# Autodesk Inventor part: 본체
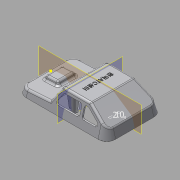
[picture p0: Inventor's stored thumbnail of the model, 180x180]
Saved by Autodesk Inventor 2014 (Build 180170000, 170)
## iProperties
Created: 2015-05
Part Number: 본체
Material: ABS 플라스틱
Document SubType Name: Modeling
Designer: Administrator
Density: 1.06 g/cm^3
Appearance: 매끄러움 - 흰색
Mass: 32.1363 g
Surface Area: 313.722 cm^2
Volume: 30.3172 cm^3
Author: Administrator
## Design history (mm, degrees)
sketch "스케치2"
  geometry: L1 (-49, -38)-(49, -38); L2 (61, -26)-(61, 26); L3 (49, 38)-(-49, 38); L4 (-61, 26)-(-61, -26); L5 (-61, -38)-(61, 38); L6 (61, -38)-(-61, 38); A1 r 12 centre (-49, 26) between (-49, 38) and (-61, 26); A2 r 12 centre (-49, -26) between (-61, -26) and (-49, -38); A3 r 12 centre (49, -26) between (49, -38) and (61, -26); A4 r 12 centre (49, 26) between (61, 26) and (49, 38); 1 further point
  constraints: 12 end point, 8 point on circle, 8 point on line, 8 tangent, 4 centre point, 3 equal radius, 2 midpoint, 2 parallel, 1 horizontal, 1 perpendicular
  dimensions: "d1" = 122 distance of L5.end L6.end; "d2" = 76 distance of L6.start L5.end; "d3" = 12 radius of A1
extrude "돌출1" new body sketch "스케치2" distance "d4" = 30; taper "d5" = -15 deg
sketch "스케치3"
  geometry: L1 (-61, 0)-(-49, 0) reference; L2 (49, 30)-(-49, 30) reference; L3 (-61, 30)-(-31, 30); L4 (-31, 30)-(-61, 10); L5 (-61, 10)-(-61, 30); 2 further points
  constraints: 6 end point, 1 horizontal, 1 midpoint, 1 perpendicular, 1 point on line, 1 vertical alignment
  dimensions: "d6" = 20 distance of L4.end L3.start; "d7" = 30 distance of L3.start L3.end
extrude "돌출2" cut sketch "스케치3" stored distance "d8" = 30; taper "d9" = 0 deg
sketch "스케치4"
  geometry: L1 (49, 0)-(61, 0) reference; L2 (61, 0)-(61, 8); L3 (61, 0)-(52.962, 30) reference; L4 (49, 30)-(-31, 30) reference; L5 (58.826, 8.114)-(19, 10.201); L6 (19, 10.201)-(6.628, 30); L7 (58.826, 8.114)-(58.826, 30); L8 (58.826, 30)-(6.628, 30); L9 (58.826, 8.114)-(61, 8); 1 further point
  constraints: 12 end point, 2 collinear, 2 perpendicular, 2 point on line
  dimensions: "d11" = 42 horizontal distance of L5.end L1.end; "d12" = 125 deg angle of L6 L5; "d13" = 3 deg angle of L5 L1; "d14" = 8 distance of L1.end L2.end
extrude "돌출3" cut sketch "스케치4" stored distance "d15" = 30; taper "d16" = 0 deg
sketch "스케치5"
  geometry: L1 (49, 38)-(-49, 38) reference; L2 (-61, 26)-(-61, -26) reference; L3 (-49, -38)-(49, -38) reference; L4 (61, -26)-(61, 26) reference; A1 r 12 centre (-49, 26) between (-49, 38) and (-61, 26) reference; A2 r 12 centre (-49, -26) between (-61, -26) and (-49, -38) reference; A3 r 12 centre (49, -26) between (49, -38) and (61, -26) reference; A4 r 12 centre (49, 26) between (61, 26) and (49, 38) reference; 1 further point
sketch "스케치6"
  geometry: L1 (-39.881, 9.267)-(-39.881, 61.267) reference; L2 (-31.476, 48.267)-(-11.476, 48.267); L3 (-11.476, 48.267)-(-11.476, 22.267); L4 (-11.476, 22.267)-(-31.476, 22.267); L5 (-31.476, 22.267)-(-31.476, 48.267); L6 (-31.476, 48.267)-(-11.476, 22.267); L7 (-11.476, 48.267)-(-31.476, 22.267); L8 (-42.476, 9.267)-(-42.476, 61.267) reference; 4 further points
  constraints: 12 end point, 4 midpoint, 2 parallel, 1 horizontal, 1 horizontal alignment, 1 perpendicular
  dimensions: "d17" = 20 distance of L3.end L4.end; "d18" = 26 distance of L2.end L3.end; "d19" = 11 distance between parallel lines of L8 L5
extrude "돌출4" join sketch "스케치6" distance "d20" = 5; taper "d21" = -20 deg
fillet "모깎기1" dims "d22" = 3
fillet "모깎기2" dims "d23" = 3
sketch "스케치7"
  geometry: 1 further point
sketch "스케치8"
  geometry: L1 (-50.664, 16.891)-(-31.756, 29.496) reference; L2 (-61, 0)-(-58.03, 11.082) reference; 1 further point
feature "쉘1" dims "d24" = 2
sketch "스케치9"
  geometry: L1 (-58.929, -26)-(-58.929, 26) reference; L2 (-49, 35.929)-(49, 35.929) reference; L3 (58.929, 26)-(58.929, -26) reference; L4 (49, -35.929)-(-49, -35.929) reference; L5 (49, 35.882)-(-49, 35.882); L6 (-58.882, 26)-(-58.882, -26); L7 (-49, -35.882)-(49, -35.882); L8 (58.882, -26)-(58.882, 26); L9 (49, 36.929)-(-49, 36.929); L10 (-59.929, 26)-(-59.929, -26); L11 (-49, -36.929)-(49, -36.929); L12 (59.929, -26)-(59.929, 26); A1 r 9.929 centre (-49, -26) between (-58.929, -26) and (-49, -35.929) reference; A2 r 9.929 centre (-49, 26) between (-49, 35.929) and (-58.929, 26) reference; A3 r 9.929 centre (49, 26) between (58.929, 26) and (49, 35.929) reference; A4 r 9.929 centre (49, -26) between (49, -35.929) and (58.929, -26) reference; A5 r 9.882 centre (-49, 26) between (-49, 35.882) and (-58.882, 26); A6 r 9.882 centre (-49, -26) between (-58.882, -26) and (-49, -35.882); A7 r 9.882 centre (49, -26) between (49, -35.882) and (58.882, -26); A8 r 9.882 centre (49, 26) between (58.882, 26) and (49, 35.882); A9 r 10.929 centre (-49, 26) between (-49, 36.929) and (-59.929, 26); A10 r 10.929 centre (-49, -26) between (-59.929, -26) and (-49, -36.929); A11 r 10.929 centre (49, -26) between (49, -36.929) and (59.929, -26); A12 r 10.929 centre (49, 26) between (59.929, 26) and (49, 36.929); 1 further point
  constraints: 16 end point, 16 point on circle, 8 centre point, 14 other
  dimensions: "d25" = 1 distance between parallel lines of L9 L2
extrude "돌출5" join sketch "스케치9" distance "d26" = 1; taper "d27" = 0 deg
sketch "스케치10"
  geometry: L1 (4.965, 30)-(-30.092, 30) reference; L2 (19, 10.201)-(7.51, 28.59) reference; L3 (-30.646, 27.832)-(-49.555, 15.226) reference; L4 (10.362, 14.59)-(4.738, 23.59); L5 (-30.242, 24.496)-(-43.742, 15.496); L6 (-31.756, 29.496)-(-50.664, 16.891) reference; L7 (-42.078, 10)-(-26.986, 10); L8 (-23.986, 13)-(-23.986, 22); L9 (-20.77, 22)-(-20.77, 13); L10 (-17.77, 10)-(7.818, 10); L11 (2.194, 25)-(-17.77, 25); L12 (-26.986, 25)-(-28.578, 25); A1 r 3 centre (-28.578, 22) between (-28.578, 25) and (-30.242, 24.496); A2 r 3 centre (-42.078, 13) between (-43.742, 15.496) and (-42.078, 10); A3 r 3 centre (-26.986, 13) between (-26.986, 10) and (-23.986, 13); A4 r 3 centre (-26.986, 22) between (-23.986, 22) and (-26.986, 25); A5 r 3 centre (-17.77, 22) between (-17.77, 25) and (-20.77, 22); A6 r 3 centre (-17.77, 13) between (-20.77, 13) and (-17.77, 10); A7 r 3 centre (2.194, 22) between (4.738, 23.59) and (2.194, 25); A8 r 3 centre (7.818, 13) between (7.818, 10) and (10.362, 14.59); 7 further points
  constraints: 16 end point, 16 point on circle, 16 tangent, 12 point on line, 8 centre point, 7 equal radius, 7 parallel, 2 perpendicular
  dimensions: "d29" = 5 distance between parallel lines of L2 L4; "d30" = 5 distance between parallel lines of L6 L5; "d31" = 28 distance of point (-51.986, 10) point (-23.986, 10); "d32" = 15 distance of point (-23.986, 10) point (-23.986, 25); "d33" = 15 distance of point (-20.77, 25) point (-20.77, 10); "d34" = 5 distance between parallel lines of L1 L11; "d35" = 5 distance between parallel lines of L1 L12; "d36" = 34 distance of point (-20.77, 10) point (13.23, 10); "d37" = 3 radius of A1
extrude "돌출6" cut sketch "스케치10" stored distance "d38" = 1; taper "d39" = 0 deg
node "작업 평면1"
sketch "스케치11"
  geometry: A1 r 4 centre (-10, 0) between (-6, 0) and (-14, 0); A2 r 4 centre (10, 0) between (14, 0) and (6, 0); A3 r 4 centre (21, 0) between (25, 0) and (17, 0); A4 r 4 centre (-21, 0) between (-17, 0) and (-25, 0); 3 further points
  constraints: 8 point on circle, 4 centre point, 13 other
  dimensions: "d41" = 8 diameter of A1; "d42" = 8 diameter of A2; "d43" = 8 diameter of A4; "d44" = 8 diameter of A3; "d45" = 20 distance of A2.centre A1.centre; "d46" = 11 distance of A1.centre A4.centre; "d47" = 11 distance of A3.centre A2.centre; "d48" = 10 distance of A2.centre point (0, 0)
extrude "돌출7" join sketch "스케치11" stored distance "d49" = 2; taper "d50" = 0 deg
chamfer "모따기1" distance "d51" = 1; stored, may be unused: second distance "d52" = 2, angle "d53" = 45 deg
sketch "스케치12"
  geometry: C1 r 3 at (0, 22); C2 r 3 at (0, -22); C3 r 3 at (40, 0); C4 r 3 at (-40, 0); 1 further point
  constraints: 4 centre point, 2 horizontal alignment, 2 vertical alignment
  dimensions: "d54" = 6 diameter of C4; "d55" = 6 diameter of C1; "d56" = 6 diameter of C3; "d57" = 6 diameter of C2; "d58" = 44 distance of C2.centre C1.centre; "d59" = 22 distance of point (0, 0) C1.centre; "d60" = 40 distance of C4.centre point (0, 0); "d61" = 40 distance of C3.centre point (0, 0)
extrude "돌출8" join sketch "스케치12" stored distance "d62" = 1; taper "d63" = 2 deg
sketch "스케치13"
  geometry: L1 (-5, -1)-(5, -1); L2 (5, -1)-(5, 1); L3 (5, 1)-(-5, 1); L4 (-5, 1)-(-5, -1); L5 (-5, -1)-(5, 1); L6 (5, -1)-(-5, 1); L7 (-5, 43)-(5, 43); L8 (5, 43)-(5, 45); L9 (5, 45)-(-5, 45); L10 (-5, 45)-(-5, 43); L11 (-5, 43)-(5, 45); L12 (5, 43)-(-5, 45); L13 (35, 21)-(45, 21); L14 (45, 21)-(45, 23); L15 (45, 23)-(35, 23); L16 (35, 23)-(35, 21); L17 (35, 21)-(45, 23); L18 (45, 21)-(35, 23); L19 (-45, 21)-(-35, 21); L20 (-35, 21)-(-35, 23); L21 (-35, 23)-(-45, 23); L22 (-45, 23)-(-45, 21); L23 (-45, 21)-(-35, 23); L24 (-35, 21)-(-45, 23); C1 r 3 at (0, 0) reference; C2 r 3 at (-40, 22) reference; C3 r 3 at (0, 44) reference; C4 r 3 at (40, 22) reference; 1 further point
  constraints: 48 end point, 8 midpoint, 8 parallel, 4 horizontal, 4 perpendicular
  dimensions: "d64" = 2 distance of L19.end L20.end; "d65" = 10 distance of L19.start L19.end; "d66" = 10 distance of L7.start L7.end; "d67" = 10 distance of L2.end L3.end; "d68" = 10 distance of L14.end L15.end; "d69" = 2 distance of L15.end L13.start; "d70" = 2 distance of L7.end L8.end; "d71" = 2 distance of L1.end L2.end
extrude "돌출9" join sketch "스케치13" stored distance "d72" = 0; taper "d73" = 0 deg
sketch "스케치14"
  geometry: L1 (2.172, 0)-(2.172, 28) reference; L2 (-7.828, 0)-(-7.828, 27.999) reference; L3 (-7.794, 28)-(27.263, 28) reference; L4 (2.172, 0)-(7.109, 28); L5 (2.172, 0)-(2.172, 28); L6 (7.109, 28)-(2.172, 28); 1 further point
  constraints: 6 end point, 2 collinear, 1 point on line
  dimensions: "d74" = 10 deg angle of L4 L5
extrude "돌출10" join sketch "스케치14" stored distance "d75" = 1; taper "d76" = 0 deg
sketch "스케치15"
  geometry: L1 (-4.519, -2.57)-(-2.913, 0) reference; L2 (-4.519, -2.57)-(-4.972, 0) reference; L3 (-4.972, 0)-(-2.913, 0) reference; 1 further point
extrude "돌출11" cut sketch "스케치15" stored distance "d77" = 1; taper "d78" = 0 deg
sketch "스케치16"
  geometry: L1 (2.172, 0)-(2.172, 12.367) reference; L2 (2.172, 0)-(6.673, 12.367); L3 (6.673, 12.367)-(2.172, 12.367); L4 (2.172, 0)-(2.172, 12.367); 1 further point
  constraints: 6 end point, 1 collinear, 1 perpendicular
  dimensions: "d79" = 20 deg angle of L2 L4
extrude "돌출12" join sketch "스케치16" stored distance "d80" = 1; taper "d81" = 0 deg
sketch "스케치17"
  geometry: L1 (6.178, 11.009)-(6.673, 12.367) reference; L2 (6.673, 12.367)-(5.537, 12.367) reference; L3 (5.89, 11.534)-(5.537, 12.367) reference; A1 r 3 centre (8.652, 12.706) between (5.89, 11.534) and (6.178, 11.009) reference; 1 further point
extrude "돌출13" cut sketch "스케치17" stored distance "d82" = 1; taper "d83" = 0 deg
sketch "스케치18"
  geometry: L1 (0, 0)-(0, 11.843) reference; L2 (-2.906, 9.978)-(-2.579, 11.049) reference; L3 (-1.675, 11.755)-(10.467, 12.391) reference; L4 (0, 0)-(-3.295, 9.052); A1 r 1 centre (-1.623, 10.756) between (-1.675, 11.755) and (-2.579, 11.049) reference; A2 r 5 centre (-7.688, 11.44) between (-7.426, 6.447) and (-2.906, 9.978) reference; 1 further point
  constraints: 2 end point, 1 point on circle
  dimensions: "d84" = 20 deg angle of L1 L4
extrude "돌출14" join sketch "스케치18" stored distance "d85" = 1; taper "d86" = 0 deg
sketch "스케치19"
  geometry: L1 (0, 0)-(0, 24.93) reference; L2 (-4.354, 27.832)-(14.555, 15.226) reference; L3 (-39.965, 28)-(-4.908, 28) reference; L4 (0, 0)-(-5.745, 28); A1 r 1 centre (-4.908, 27) between (-4.354, 27.832) and (-4.908, 28) reference; 1 further point
  constraints: 2 end point, 1 point on line
  dimensions: "d87" = 11.5941 deg angle of L1 L4
extrude "돌출15" join sketch "스케치19" stored distance "d88" = 1; taper "d89" = 0 deg
sketch "스케치20"
  geometry: L1 (2.172, 0)-(2.172, 18.263) reference; L2 (-12.182, 27.832)-(6.726, 15.226) reference; L3 (2.172, 0)-(7.521, 14.697); L4 (6.726, 15.226)-(7.521, 14.697); 1 further point
  constraints: 4 end point, 1 collinear, 1 point on line
  dimensions: "d90" = 20 deg angle of L3 L1
extrude "돌출16" join sketch "스케치20" stored distance "d91" = 1; taper "d92" = 0 deg
sketch "스케치21"
  geometry: L1 (-2.828, 23)-(-5, 23) reference; L2 (-5, 23)-(-5, 21) reference; L3 (-5, 21)-(-2.828, 21) reference; L4 (2.828, 21)-(5, 21) reference; L5 (5, 21)-(5, 23) reference; L6 (5, 23)-(2.828, 23) reference; L7 (-42.828, 1)-(-45, 1) reference; L8 (-45, 1)-(-45, -1) reference; L9 (-45, -1)-(-42.828, -1) reference; L10 (-37.172, -1)-(-35, -1) reference; L11 (-35, -1)-(-35, 1) reference; L12 (-35, 1)-(-37.172, 1) reference; L13 (37.172, 1)-(35, 1) reference; L14 (35, 1)-(35, -1) reference; L15 (35, -1)-(37.172, -1) reference; L16 (42.828, -1)-(45, -1) reference; L17 (45, -1)-(45, 1) reference; L18 (45, 1)-(42.828, 1) reference; C1 r 3 at (0, -22); C2 r 3 at (0, 22); C3 r 3 at (40, 0); A1 r 3 centre (0, -22) between (2.828, -21) and (-2.828, -21) reference; A2 r 3 centre (0, -22) between (-2.828, -23) and (2.828, -23) reference; A3 r 3 centre (0, 22) between (2.828, 23) and (-2.828, 23) reference; A4 r 3 centre (0, 22) between (-2.828, 21) and (2.828, 21) reference; A5 r 3 centre (-40, 0) between (-37.172, 1) and (-42.828, 1) reference; A6 r 3 centre (-40, 0) between (-42.828, -1) and (-37.172, -1) reference; A7 r 3 centre (40, 0) between (42.828, 1) and (37.172, 1) reference; A8 r 3 centre (40, 0) between (37.172, -1) and (42.828, -1) reference; 1 further point
  constraints: 3 centre point, 3 coincident, 3 concentric
  node "투영된 루프4"
  node "투영된 루프5"
  node "투영된 루프6"
sketch "스케치22"
  geometry: L1 (-42.828, 1)-(-45, 1) reference; L2 (-45, 1)-(-45, -1) reference; L3 (-45, -1)-(-42.828, -1) reference; L4 (-37.172, -1)-(-35, -1) reference; L5 (-35, -1)-(-35, 1) reference; L6 (-35, 1)-(-37.172, 1) reference; A1 r 3 centre (-40, 0) between (-37.172, 1) and (-42.828, 1) reference; A2 r 3 centre (-40, 0) between (-42.828, -1) and (-37.172, -1) reference; 1 further point
sketch "스케치23"
  geometry: L1 (-42.828, 1)-(-45, 1) reference; L2 (-45, 1)-(-45, -1) reference; L3 (-45, -1)-(-42.828, -1) reference; L4 (-37.172, -1)-(-35, -1) reference; L5 (-35, -1)-(-35, 1) reference; L6 (-35, 1)-(-37.172, 1) reference; C1 r 3 at (-40, 0); A1 r 3 centre (-40, 0) between (-37.172, 1) and (-42.828, 1) reference; A2 r 3 centre (-40, 0) between (-42.828, -1) and (-37.172, -1) reference; 1 further point
  constraints: 1 centre point, 1 coincident, 1 concentric
sketch "스케치24"
  geometry: L1 (2.172, 0)-(0, 0) reference; L2 (2.172, 0)-(7.109, 28) reference; L3 (-7.828, 0)-(-11.793, 22.486) reference; L4 (-8.181, 2)-(2.524, 2); L5 (0, 0)-(-5.657, 0) reference; L6 (-5.657, 0)-(-5.657, 2); L7 (0, 0)-(0, 2); L8 (-8.181, 2)-(-7.828, 0); L9 (-5.657, 0)-(-7.828, 0); L10 (0, 0)-(2.172, 0); L11 (2.524, 2)-(2.172, 0); 1 further point
  constraints: 14 end point, 4 point on line, 3 collinear, 2 parallel, 2 perpendicular
  dimensions: "d93" = 2 distance between parallel lines of L5 L4
extrude "돌출17" cut sketch "스케치24" stored distance "d94" = 2; taper "d95" = 0 deg
sketch "스케치25"
  geometry: L1 (-1.675, 11.755)-(1.733, 11.933) reference; L2 (-2.906, 9.978)-(-2.579, 11.049) reference; L3 (-3.295, 9.052)-(0, 0) reference; L4 (2.172, 0)-(0, 0) reference; L5 (10, 0)-(13.239, 8.899) reference; L6 (-0.728, 2)-(10.728, 2); L7 (7.828, 0)-(2.172, 0) reference; L8 (-0.728, 2)-(0, 0); L9 (2.172, 0)-(2.098, 2); L10 (8.28, 12.277)-(10, 12.367) reference; L11 (10, 0)-(7.828, 0) reference; L12 (10, 0)-(13.239, 8.899) reference; L13 (11.44, 11.783)-(11.878, 10.753) reference; L14 (10.746, 12.367)-(10, 12.367) reference; L15 (0, 0)-(2.172, 0); A1 r 1 centre (-1.623, 10.756) between (-1.675, 11.755) and (-2.579, 11.049) reference; A2 r 5 centre (-7.688, 11.44) between (-3.295, 9.052) and (-2.906, 9.978) reference; A3 r 5 centre (16.48, 12.706) between (11.878, 10.753) and (13.239, 8.899) reference; A4 r 1 centre (10.52, 11.393) between (11.44, 11.783) and (10.746, 12.367) reference; 1 further point
  constraints: 8 end point, 3 point on line, 2 collinear, 1 parallel, 3 other
  dimensions: "d96" = 2 distance between parallel lines of L7 L6
sketch "스케치26"
  geometry: L1 (-1.675, 11.755)-(1.733, 11.933) reference; L2 (-2.906, 9.978)-(-2.579, 11.049) reference; L3 (-3.295, 9.052)-(0, 0) reference; L4 (2.172, 0)-(0, 0) reference; L5 (8.28, 12.277)-(10, 12.367) reference; L6 (10, 0)-(7.828, 0) reference; L7 (10, 0)-(13.239, 8.899) reference; L8 (11.44, 11.783)-(11.878, 10.753) reference; L9 (10.746, 12.367)-(10, 12.367) reference; A1 r 1 centre (-1.623, 10.756) between (-1.675, 11.755) and (-2.579, 11.049) reference; A2 r 5 centre (-7.688, 11.44) between (-3.295, 9.052) and (-2.906, 9.978) reference; A3 r 5 centre (16.48, 12.706) between (11.878, 10.753) and (13.239, 8.899) reference; A4 r 1 centre (10.52, 11.393) between (11.44, 11.783) and (10.746, 12.367) reference; 1 further point
  constraints: 2 other
sketch "스케치27"
  geometry: L1 (-1.675, 11.755)-(1.733, 11.933) reference; L2 (-2.906, 9.978)-(-2.579, 11.049) reference; L3 (-3.295, 9.052)-(0, 0) reference; L4 (2.172, 0)-(0, 0) reference; L5 (-3.295, 9.052)-(0, 0) reference; L6 (2.172, 0)-(0, 0) reference; L7 (2.172, 0)-(2.098, 2) reference; L8 (-0.728, 2)-(0, 0); L9 (2.172, 0)-(0, 0); L10 (2.172, 0)-(2.098, 2); A1 r 1 centre (-1.623, 10.756) between (-1.675, 11.755) and (-2.579, 11.049) reference; A2 r 5 centre (-7.688, 11.44) between (-3.295, 9.052) and (-2.906, 9.978) reference; 2 further points
  constraints: 6 end point, 3 collinear, 1 point on line, 1 other
sketch "스케치28"
  geometry: L1 (-5.745, 28)-(0, 0) reference; L2 (2.172, 0)-(0, 0) reference; L3 (-0.41, 2)-(2.098, 2); 2 further points
  constraints: 2 end point, 1 parallel, 1 point on line, 2 other
  dimensions: "d97" = 2 distance between parallel lines of L3 L2
extrude "돌출18" cut sketch "스케치28" stored distance "d98" = 2; taper "d99" = 0 deg
sketch "스케치29"
  geometry: L1 (2.172, 0)-(0, 0) reference; L2 (2.172, 0)-(7.521, 14.697) reference; L3 (0.074, 2)-(2.9, 2); 2 further points
  constraints: 2 end point, 1 parallel, 1 point on line, 2 other
  dimensions: "d100" = 2 distance between parallel lines of L1 L3
extrude "돌출19" cut sketch "스케치29" stored distance "d101" = 2; taper "d102" = 0 deg
sketch "스케치30"
  geometry: L1 (-2.828, -21)-(-2.828, -23) reference; L2 (2.828, -23)-(2.828, -21) reference; A1 r 3 centre (0, -22) between (-2.828, -23) and (2.828, -23) reference; A2 r 3 centre (0, -22) between (2.828, -21) and (-2.828, -21) reference; 1 further point
hole "구멍1" sketch "스케치21" diameter "d103" = 3.242; stored, may be unused: countersink angle "d107" = 90 deg, drill point angle "d109" = 118 deg; dims "d104" = 9, "d105" = 4, "d106" = 2, "d108" = 11
sketch "스케치31"
  geometry: L1 (-1.675, 11.755)-(1.733, 11.933) reference; L2 (-2.906, 9.978)-(-2.579, 11.049) reference; L3 (-3.295, 9.052)-(0, 0) reference; L4 (2.172, 0)-(0, 0) reference; A1 r 1 centre (-1.623, 10.756) between (-1.675, 11.755) and (-2.579, 11.049) reference; A2 r 5 centre (-7.688, 11.44) between (-3.295, 9.052) and (-2.906, 9.978) reference; 1 further point
  constraints: 1 other
sketch "스케치32"
  geometry: L1 (-1.675, 11.755)-(1.733, 11.933) reference; L2 (-2.906, 9.978)-(-2.579, 11.049) reference; L3 (-3.295, 9.052)-(0, 0) reference; L4 (2.172, 0)-(0, 0) reference; L5 (-0.736, 2.021)-(0, 0); A1 r 1 centre (-1.623, 10.756) between (-1.675, 11.755) and (-2.579, 11.049) reference; A2 r 5 centre (-7.688, 11.44) between (-3.295, 9.052) and (-2.906, 9.978) reference; 1 further point
  constraints: 2 end point, 1 collinear, 1 point on line, 1 other
sketch "스케치33"
  geometry: L1 (2.172, 0)-(0, 0) reference; L2 (-5.657, 0)-(-7.828, 0) reference; L3 (-8.556, 2)-(-7.828, 0) reference; L4 (-8.556, 2)-(2.9, 2) reference; L5 (-5.657, 0)-(-5.731, 2) reference; 3 further points
extrude "돌출20" cut sketch "스케치33" stored distance "d110" = 2; taper "d111" = 0 deg
sketch "스케치34"
  geometry: L1 (0.451, 12.277)-(2.172, 12.367) reference; L2 (2.172, 0)-(0, 0) reference; L3 (2.172, 0)-(5.411, 8.899) reference; L4 (3.612, 11.783)-(4.049, 10.753) reference; L5 (2.917, 12.367)-(2.172, 12.367) reference; L6 (2.172, 0)-(0, 0) reference; L7 (2.172, 0)-(5.411, 8.899) reference; L8 (0, 0)-(2.172, 0); L9 (2.917, 2.048)-(2.172, 0); L10 (0, 0)-(0, 0); A1 r 5 centre (8.652, 12.706) between (4.049, 10.753) and (5.411, 8.899) reference; A2 r 1 centre (2.691, 11.393) between (3.612, 11.783) and (2.917, 12.367) reference; 1 further point
  constraints: 6 end point, 2 collinear, 1 perpendicular, 1 point on line, 2 other
sketch "스케치35"
  geometry: L1 (2.172, 12.367)-(0.451, 12.277) reference; L2 (2.917, 12.367)-(2.172, 12.367) reference; L3 (4.049, 10.753)-(3.612, 11.783) reference; L4 (2.172, 0)-(5.411, 8.899) reference; L5 (0, 0)-(2.172, 0) reference; L6 (0.073, 1.985)-(2.894, 1.985); A1 r 1 centre (2.691, 11.393) between (3.612, 11.783) and (2.917, 12.367) reference; A2 r 5 centre (8.652, 12.706) between (4.049, 10.753) and (5.411, 8.899) reference; 3 further points
  constraints: 2 end point, 1 parallel, 1 point on line, 4 other
extrude "돌출21" cut sketch "스케치35" stored distance "d112" = 2; taper "d113" = 0 deg
hole "구멍2" diameter "d116" = 3.242; stored, may be unused: countersink angle "d120" = 90 deg, drill point angle "d122" = 118 deg; dims "d114" = 10, "d115" = 10, "d117" = 9, "d118" = 4, "d119" = 2, "d121" = 11
sketch "스케치36"
  geometry: L1 (61, 26)-(61, -26) reference; 2 further points
  constraints: 1 horizontal alignment, 1 other
  dimensions: "d123" = 50 distance from line of L1 point (11, 0)
feature "엠보싱1" sketch "스케치36" dims "d124" = 0.5, "d125" = 0
sketch "스케치37"
  geometry: L1 (-45.728, 2)-(-50.349, 14.697) reference; L2 (-42.902, 2)-(-45.728, 2) reference; L3 (-45.728, 2)-(-48.217, 16.118); L4 (-31.756, 29.496)-(-50.664, 16.891) reference; L5 (-48.217, 16.118)-(-49.555, 15.226); L6 (-49.555, 15.226)-(-50.349, 14.697); 1 further point
  constraints: 6 end point, 1 parallel
  dimensions: "d126" = 100 deg angle of L2 L3; "d127" = 2 distance between parallel lines of L4 L5
extrude "돌출22" join sketch "스케치37" stored distance "d128" = 10; taper "d129" = 0 deg
sketch "스케치38"
  geometry: L1 (0, 2)-(2.826, 2) reference; L2 (0, 0)-(0, 2) reference; L3 (2.826, 0)-(0, 0) reference; L4 (2.826, 0)-(2.826, 2) reference; L5 (11.138, 2)-(11.138, 0) reference; 1 further point
sketch "스케치39"
  geometry: L1 (0, 2)-(2.826, 2) reference; L2 (0, 0)-(0, 2) reference; L3 (2.826, 0)-(0, 0) reference; L4 (2.826, 0)-(2.826, 2) reference; L5 (0.728, 2)-(10.728, 2); L6 (10.728, 2)-(10.728, 0); L7 (10.728, 0)-(0.728, 0); L8 (0.728, 0)-(0.728, 2); C1 r 1.621 at (5.728, 1) reference; 6 further points
  constraints: 8 end point, 3 coincident, 2 midpoint, 2 parallel, 1 horizontal, 1 horizontal alignment, 1 perpendicular, 1 vertical alignment
  dimensions: "d130" = 10 distance of L5.start L5.end; "d131" = 2 distance of L5.end L6.end
sketch "스케치40"
  geometry: L1 (2.826, 0)-(0, 0) reference; L2 (7.447, -12.697)-(0.631, -17.241) reference; L3 (2.826, 0)-(7.447, -12.697) reference; L4 (2.098, 0)-(-7.902, 0) reference; L5 (2.098, 0)-(2.938, -4.766); L6 (-7.902, 0)-(-10.507, -14.77); L7 (7.762, -14.891)-(-11.147, -27.496) reference; L8 (-12.811, -26)-(-47.868, -26) reference; L9 (-13.647, -26)-(-8.313, 0) reference; L10 (-12.811, -26)-(-13.647, -26); L11 (-8.313, 0)-(-7.902, 0); L12 (2.938, -4.766)-(4.664, -14.552); L13 (7.447, -12.697)-(4.664, -14.552); L14 (2.938, 0)-(2.098, 0); L15 (-10.507, -14.77)-(-12.811, -26); 2 further points
  constraints: 16 end point, 4 collinear, 1 parallel, 1 point on line, 1 other
  dimensions: "d132" = 100 deg angle of L5 L1; "d133" = 100 deg angle of L4 L6
extrude "돌출23" cut sketch "스케치40" stored distance "d134" = 10; taper "d135" = 0 deg
sketch "스케치41"
  geometry: L1 (-42.828, 1)-(-42.828, -1) reference; L2 (-37.172, -1)-(-37.172, 1) reference; C1 r 3 at (-40, 0); A1 r 3 centre (-40, 0) between (-42.828, -1) and (-37.172, -1) reference; A2 r 3 centre (-40, 0) between (-37.172, 1) and (-42.828, 1) reference; 1 further point
  constraints: 1 centre point, 1 coincident, 1 concentric
extrude "돌출24" join sketch "스케치41" distance "d136" = 2; taper "d137" = 2 deg
sketch "스케치42"
  geometry: L1 (-2.828, -21)-(-2.828, -23) reference; L2 (2.828, -23)-(2.828, -21) reference; C1 r 3 at (0, -22); A1 r 3 centre (0, -22) between (-2.828, -23) and (2.828, -23) reference; A2 r 3 centre (0, -22) between (2.828, -21) and (-2.828, -21) reference; 1 further point
  constraints: 1 centre point, 1 coincident, 1 concentric
extrude "돌출25" join sketch "스케치42" distance "d138" = 2; taper "d139" = 2 deg
node "솔리드1"
mirror "대칭1"
mirror "대칭2"
mirror "대칭3"
mirror "대칭4"
mirror "대칭5"
node "투영된 루프1"
node "투영된 루프2"
node "투영된 루프3"
node "투영된 루프7"
node "작업 평면2"
node "작업 평면3"
other parameters: "d28" = 5, "d40" = -63
